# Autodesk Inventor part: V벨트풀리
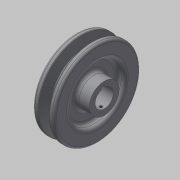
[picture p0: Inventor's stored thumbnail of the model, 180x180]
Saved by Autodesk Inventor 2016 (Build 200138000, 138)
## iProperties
Created: 2015-11
Part Number: V벨트풀리
Material: 강철, 탄소
Document SubType Name: Modeling
Designer: mduedu
Density: 1 g/cm^3
Appearance: 기본값
Author: mduedu
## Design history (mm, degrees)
sketch "스케치1"
  geometry: L1 (-9.5, 0)-(9.5, 0); L2 (0, 0)-(0, 37.7); L3 (-4.825, 37.7)-(-9.5, 37.7); L4 (-9.5, 37.7)-(-9.5, 0); L5 (0, 28.7)-(-2.074, 28.7); L6 (-2.074, 28.7)-(-4.825, 37.7); L7 (4.825, 37.7)-(9.5, 37.7); L8 (9.5, 37.7)-(9.5, 0); L9 (0, 28.7)-(2.074, 28.7); L10 (2.074, 28.7)-(4.825, 37.7); L11 (-9.5, 35)-(9.5, 35); 3 further points
  constraints: 22 end point, 7 point on line, 4 perpendicular, 3 symmetric about line, 1 coincident, 1 horizontal, 1 horizontal alignment, 1 midpoint, 1 vertical
  dimensions: "d0" = 19 distance of L1.start L1.end; "d2" = 75.4 diameter of L2.end L1 (derived); "d3" = 34 deg angle of L10 L6; "d4" = 6.3 distance between parallel lines of L11 L9; "d5" = 2.7 distance between parallel lines of L7 L11; "d6" = 8 distance of point (4, 35) point (-4, 35); "d7" = 70 diameter of L11 L1
revolve "회전1" sketch "스케치1" stored, may be unused: angle "d8" = 90 deg
sketch "스케치2"
  geometry: C1 r 24 at (0, 0); C2 r 13 at (0, 0); 1 further point
  constraints: 2 centre point, 2 coincident
  dimensions: "d9" = 48 diameter of C1; "d10" = 26 diameter of C2
extrude "돌출1" cut sketch "스케치2" distance "d11" = 6; taper "d12" = 0 deg
extrude "돌출3" join sketch "스케치2" distance "d37" = 6; taper "d38" = 0 deg
fillet "모깎기1" dims "d13" = 3
fillet "모깎기2" dims "d14" = 3
fillet "모깎기3" dims "d15" = 1, "d16" = 0.5, "d17" = 2
hole "구멍1" diameter "d20" = 16; stored, may be unused: countersink angle "d24" = 90 deg, drill point angle "d26" = 118 deg; dims "d21" = 6, "d22" = 4, "d23" = 2, "d25" = 8, "d53" = 10, "d54" = 10
sketch "스케치3"
  geometry: L1 (-2.5, 0)-(2.5, 0); L2 (2.5, 0)-(2.5, 10.3); L3 (2.5, 10.3)-(-2.5, 10.3); L4 (-2.5, 10.3)-(-2.5, 0); 2 further points
  constraints: 8 end point, 2 parallel, 1 coincident, 1 horizontal, 1 midpoint, 1 perpendicular
  dimensions: "d27" = 5 distance of L2.end L3.end; "d29" = 10.3 distance of L3.end L1.start
extrude "돌출2" cut sketch "스케치3" stored distance "d30" = 6; taper "d31" = 0 deg
chamfer "모따기1" distance "d32" = 1; stored, may be unused: second distance "d33" = 2, angle "d34" = 45 deg
node "작업 평면1"
sketch "스케치4"
  geometry: L1 (19, -27)-(19, 27) reference; 2 further points
  constraints: 1 horizontal alignment
  dimensions: "d52" = 22 distance from line of L1 point (-3, 0)
hole "구멍2" sketch "스케치4" at (-3, 0) diameter "d42" = 2.459; stored, may be unused: countersink angle "d46" = 90 deg, drill point angle "d48" = 118 deg; dims "d43" = 6, "d44" = 4, "d45" = 2, "d47" = 8
node "솔리드1"
mirror "대칭1"
